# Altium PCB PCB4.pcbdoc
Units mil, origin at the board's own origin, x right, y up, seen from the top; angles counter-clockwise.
Board outline 2790 x 2690 mil, 2 copper layers (Top Layer, Bottom Layer); 2 components, 14 nets, 61 pads, 83 vias.
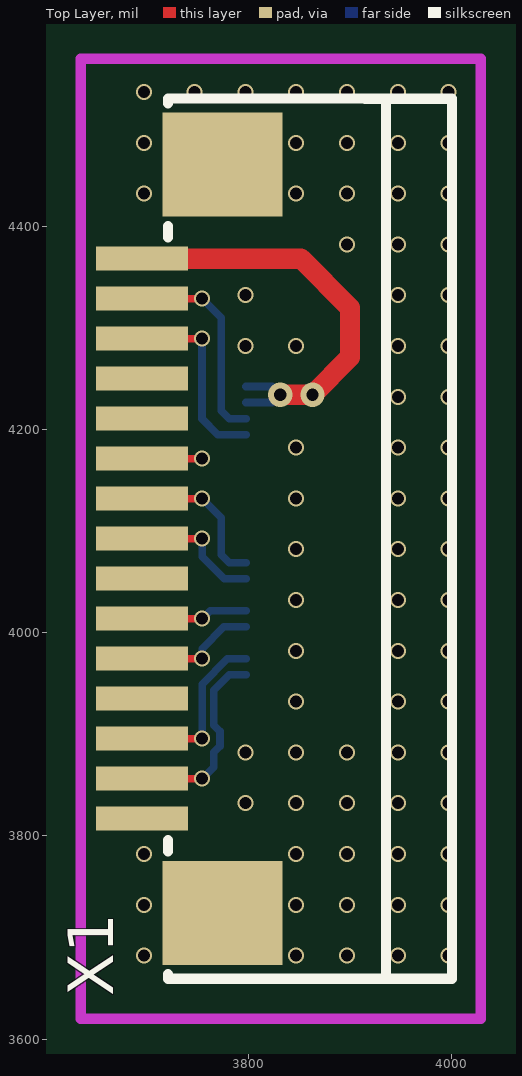
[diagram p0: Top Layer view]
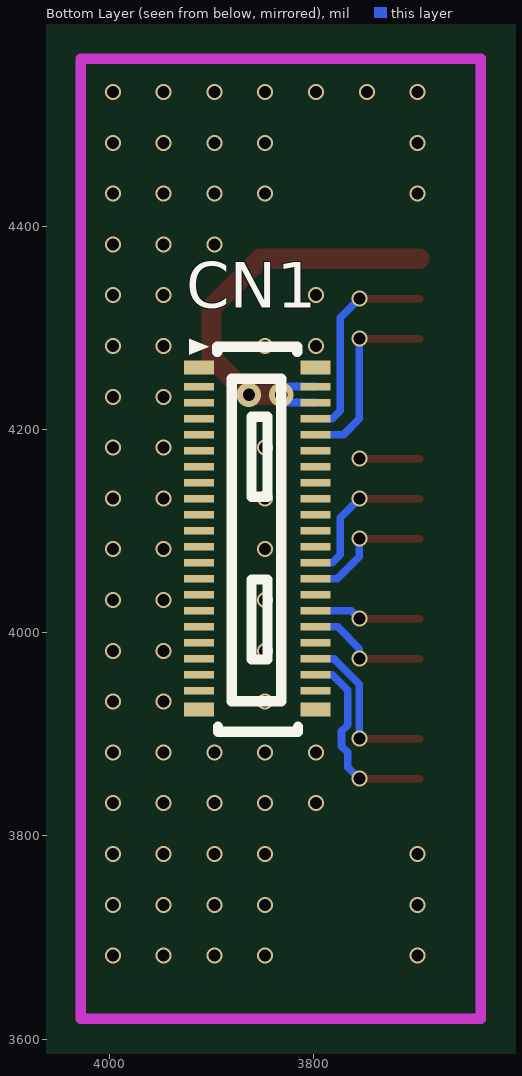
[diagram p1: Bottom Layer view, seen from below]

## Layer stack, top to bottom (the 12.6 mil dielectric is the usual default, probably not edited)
Top Layer: signal copper (thickness not stored)
Dielectric: dielectric 12.6, FR-4, Dk 4.8
Bottom Layer: signal copper (thickness not stored)

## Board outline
5540,2750 2750,2750 2750,5440 5540,5440

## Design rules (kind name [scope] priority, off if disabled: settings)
BoardOutlineClearance copperThickness1oz [All] p0: genericclearance=10 ignorepadtopadclearanceinfootprint=FALSE except(0: Arc-SplitContinuation Track-SplitContinuation SMDPad-SplitContinuation THPad-SplitContinuation Via-SplitContinuation Fill-SplitContinuation Poly-SplitContinuation Region-SplitContinuation Text-SplitContinuation; 6: Track-CutoutEdge SMDPad-CutoutEdge THPad-CutoutEdge Via-CutoutEdge Region-CutoutEdge; 11.8: Track-OutlineEdge SMDPad-OutlineEdge THPad-OutlineEdge Via-OutlineEdge Fill-OutlineEdge Region-OutlineEdge Poly-OutlineEdge Text-OutlineEdge Fill-CutoutEdge)
BoardOutlineClearance copperThickness2oz [All] p0: genericclearance=10 ignorepadtopadclearanceinfootprint=FALSE except(0: Arc-SplitContinuation Track-SplitContinuation SMDPad-SplitContinuation THPad-SplitContinuation Via-SplitContinuation Fill-SplitContinuation Poly-SplitContinuation Region-SplitContinuation Text-SplitContinuation; 6: Track-CutoutEdge SMDPad-CutoutEdge THPad-CutoutEdge Via-CutoutEdge Region-CutoutEdge; 11.8: Track-OutlineEdge SMDPad-OutlineEdge THPad-OutlineEdge Via-OutlineEdge Fill-OutlineEdge Region-OutlineEdge Poly-OutlineEdge Text-OutlineEdge Fill-CutoutEdge)
Clearance copperThickness1oz [(InNet('GND') OR InNet('CSID0N') OR InNet('CSID0P') OR InNet('CSID1N') OR InNet('CSID1P') OR InNet('CSICN') OR InNet('CSICP') OR InNet('CSID2N') OR InNet('CSID2P') OR InNet('CSID3N') OR InNet('CSID3P') OR InNet('HOST_SCL') OR InNet('HOST_SDA') OR InNet('3V3'))] p1: gap=7 ignorepadtopadclearanceinfootprint=FALSE except(4: Track-Track; 6: Track-SMDPad SMDPad-SMDPad Track-THPad SMDPad-THPad THPad-THPad Track-Via SMDPad-Via THPad-Via Via-Via SMDPad-Fill THPad-Fill Via-Fill Fill-Fill Track-Region SMDPad-Region THPad-Region Via-Region Region-Region Track-Poly SMDPad-Poly THPad-Poly Via-Poly Fill-Poly Region-Poly Poly-Poly Track-Text SMDPad-Text THPad-Text Via-Text Fill-Text Region-Text Poly-Text Text-Text; 6.9: Track-Hole SMDPad-Hole THPad-Hole Via-Hole Fill-Hole Region-Hole Poly-Hole Text-Hole Sheet-Hole; 11.8: Track-Fill Fill-Region Track-Sheet SMDPad-Sheet THPad-Sheet Via-Sheet Fill-Sheet Region-Sheet Poly-Sheet Text-Sheet)
Clearance copperThickness2oz [All] p1: gap=7 ignorepadtopadclearanceinfootprint=FALSE except(6: Track-SMDPad SMDPad-SMDPad Track-THPad SMDPad-THPad THPad-THPad Track-Via SMDPad-Via THPad-Via Via-Via SMDPad-Fill THPad-Fill Via-Fill Fill-Fill Track-Region SMDPad-Region THPad-Region Via-Region Region-Region Track-Poly SMDPad-Poly THPad-Poly Via-Poly Fill-Poly Region-Poly Poly-Poly Track-Text SMDPad-Text THPad-Text Via-Text Fill-Text Region-Text Poly-Text Text-Text; 6.9: Track-Hole SMDPad-Hole THPad-Hole Via-Hole Fill-Hole Region-Hole Poly-Hole Text-Hole Sheet-Hole; 8: Track-Track; 11.8: Track-Fill Fill-Region Track-Sheet SMDPad-Sheet THPad-Sheet Via-Sheet Fill-Sheet Region-Sheet Poly-Sheet Text-Sheet)
DiffPairsRouting differentialPair [All] p1: maxuncoupledlength=10 minlimit=6 maxlimit=6 mostfreqgap=6 toplayer_minwidth=5 toplayer_prefwidth=10 toplayer_maxwidth=100 bottomlayer_minwidth=5 bottomlayer_prefwidth=10 bottomlayer_maxwidth=100
PasteMaskExpansion pasteMaskExpansion [All] p1: expansion=0
PlaneConnect innerPlane [All] p1: planeconnectstyle=Relief reliefexpansion=20 reliefentries=4 reliefconductorwidth=10 reliefairgap=10
PolygonConnect copperRegion [All] p1: connectstyle=Direct reliefentries=4 reliefconductorwidth=10 polygonreliefangle="90 Angle" airgapwidth=10
RoutingVias viaSize [All] p1: viastyle="Through Hole" holewidth=11.811 minholewidth=11.8 maxholewidth=248 width=15.748 minwidth=15.748 maxwidth=393.7
SolderMaskExpansion solderMaskExpansion [All] p1: useseparateexpansions=TRUE expansion=2 expansionbottom=2
Width copperThickness1oz [All] p1: maxlimit=100 minlimit=5 preferedwidth=10
Width copperThickness2oz [All] p1: maxlimit=100 minlimit=8 preferedwidth=10

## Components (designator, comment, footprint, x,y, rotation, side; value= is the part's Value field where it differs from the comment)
CN1 "DF40C-40DP-0.4V(51)" CONN-SMD_DF40C-40DP-0.4V 3855,4092.56 r270 bottom
X1 "AFA07-S15ECA-00" FPC-SMD_15P-P1.00_JS_AFA07-S15XXX 3735,4092.56 r90 top

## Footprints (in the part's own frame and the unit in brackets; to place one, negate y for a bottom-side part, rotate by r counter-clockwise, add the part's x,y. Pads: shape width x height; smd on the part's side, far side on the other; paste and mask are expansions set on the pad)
CONN-SMD_DF40C-40DP-0.4V [mm]
  rect 0.19x0.75 smd: 1(-3.8,-1.455) 2(-3.8,1.455) 3(-3.4,-1.455) 4(-3.4,1.455) 5(-3,-1.455) 6(-3,1.455) 7(-2.6,-1.455) 8(-2.6,1.455) 9(-2.2,-1.455) 10(-2.2,1.455) 11(-1.8,-1.455) 12(-1.8,1.455) 13(-1.4,-1.455) 14(-1.4,1.455) 15(-1,-1.455) 16(-1,1.455) 17(-0.6,-1.455) 18(-0.6,1.455) 19(-0.2,-1.455) 20(-0.2,1.455) 21(0.2,-1.455) 22(0.2,1.455) 23(0.6,-1.455) 24(0.6,1.455) 25(1,-1.455) 26(1,1.455) 27(1.4,-1.455) 28(1.4,1.455) 29(1.8,-1.455) 30(1.8,1.455) 31(2.2,-1.455) 32(2.2,1.455) 33(2.6,-1.455) 34(2.6,1.455) 35(3,-1.455) 36(3,1.455) 37(3.4,-1.455) 38(3.4,1.455) 39(3.8,-1.455) 40(3.8,1.455)
  rect 0.35x0.75 smd: 41(4.275,-1.455) 42(4.275,1.455) 43(-4.275,1.455) 44(-4.275,-1.455)
  silkscreen extent -5,-1.7 4.83,1.02
FPC-SMD_15P-P1.00_JS_AFA07-S15XXX [mm]
  rect 0.6x2.3 smd: 1(-7,1.009) 2(-6,1.009) 3(-5,1.009) 4(-4,1.009) 5(-3,1.009) 6(-2,1.009) 7(-1,1.009) 8(0,1.009) 9(1,1.009) 10(2,1.01) 11(3,1.01) 12(4,1.01) 13(5,1.01) 14(6,1.009) 15(7,1.01)
  rect 2.6x3 smd: 16(9.352,-1.01) 17(-9.352,-1.01)
  silkscreen extent -11,-6.74 11,0.36

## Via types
v1: diameter 15.75, hole 11.81, Top Layer to Bottom Layer, 81 vias
v2: diameter 24.02, hole 12.01, Top Layer to Bottom Layer, 2 vias

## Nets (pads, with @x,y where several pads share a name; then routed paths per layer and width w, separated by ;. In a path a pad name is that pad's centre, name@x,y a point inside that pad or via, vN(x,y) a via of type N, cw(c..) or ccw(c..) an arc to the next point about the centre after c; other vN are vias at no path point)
3V3: CN1.2 CN1.4 X1.15 | length 431.2
  Top Layer w20: X1.15 3851.85,4368.15 3900,4320 3900,4271.2 v2(3863.16,4234.36) v2@3831.43,4234.36
  Bottom Layer w7.9: CN1.4 3823.48,4226.42 v2(3831.38,4234.31) 3823.52,4242.17 CN1.2
CSICN: CN1.26 X1.8 | length 129
  Top Layer w7.5: X1.8 v1(3754.44,4092.56)
  Bottom Layer w7.5: v1(3754.44,4092.56) 3754.44,4075 3776.26,4053.19 CN1.26
CSICP: CN1.24 X1.9 | length 149.8
  Top Layer w7.5: X1.9 v1(3754.44,4131.93)
  Bottom Layer w7.5: v1(3754.44,4131.93) 3773.2,4113.18 3773.2,4076.91 3781.17,4068.94 CN1.24
CSID0N: CN1.38 X1.2 | length 194.2
  Top Layer w7.5: X1.2 v1(3754.44,3856.34)
  Bottom Layer w7.5: v1(3754.44,3856.34) 3765.94,3867.84 3765.94,3882.29 3772.07,3888.41 3772.07,3903.01 3765.94,3909.14 3765.94,3943.48 3781.17,3958.71 CN1.38
CSID0P: CN1.36 X1.3 | length 166.5
  Top Layer w7.5: X1.3 v1(3754.44,3895.71)
  Bottom Layer w7.5: v1(3754.44,3895.71) 3754.44,3949.44 3779.45,3974.45 CN1.36
CSID1N: CN1.32 X1.5 | length 121.3
  Top Layer w7.5: X1.5 v1(3754.44,3974.45)
  Bottom Layer w7.5: v1(3754.44,3974.45) 3754.44,3984.44 3775.95,4005.95 CN1.32
CSID1P: CN1.30 X1.6 | length 105.7
  Top Layer w7.5: X1.6 v1(3754.44,4013.81)
  Bottom Layer w7.5: v1(3754.44,4013.81) 3762.32,4021.7 CN1.30
CSID2N: CN1.20
CSID2P: CN1.18
CSID3N: CN1.14
CSID3P: CN1.12
GND: CN1.10 CN1.16 CN1.22 CN1.28 CN1.34 CN1.40 CN1.41 CN1.42 CN1.43 CN1.44 X1.1 X1.4 X1.7 X1.10 X1.16 X1.17 | length 59.1
  Top Layer w7.5: X1.10 v1(3754.38,4171.3)
  other v1: 3697.1,3682.22 3847.1,3682.22 3897.1,3682.22 3947.1,3682.22 3997.1,3682.22 3697.1,3732.22 3847.1,3732.22 3897.1,3732.22 3947.1,3732.22 3997.1,3732.22 3697.1,3782.22 3847.1,3782.22 3897.1,3782.22 3947.1,3782.22 3997.1,3782.22 3797.1,3832.22 3847.1,3832.22 3897.1,3832.22 3947.1,3832.22 3997.1,3832.22 3797.1,3882.22 3847.1,3882.22 3897.1,3882.22 3947.1,3882.22 3997.1,3882.22 3847.1,3932.22 3947.1,3932.22 3997.1,3932.22 3847.1,3982.22 3947.1,3982.22 3997.1,3982.22 3847.1,4032.22 3947.1,4032.22 3997.1,4032.22 3847.1,4082.22 3947.1,4082.22 3997.1,4082.22 3847.1,4132.22 3947.1,4132.22 3997.1,4132.22 3847.1,4182.22 3947.1,4182.22 3997.1,4182.22 3947.1,4232.22 3997.1,4232.22 3797.1,4282.22 3847.1,4282.22 3947.1,4282.22 3997.1,4282.22 3797.1,4332.22 3947.1,4332.22 3997.1,4332.22 3897.1,4382.22 3947.1,4382.22 3997.1,4382.22 3697.1,4432.22 3847.1,4432.22 3897.1,4432.22 3947.1,4432.22 3997.1,4432.22 3697.1,4482.22 3847.1,4482.22 3897.1,4482.22 3947.1,4482.22 3997.1,4482.22 3697.1,4532.22 3747.1,4532.22 3797.1,4532.22 3847.1,4532.22 3897.1,4532.22 3947.1,4532.22 3997.1,4532.22
HOST_SCL: CN1.8 X1.13 | length 187.8
  Top Layer w7.5: X1.13 v1(3754.38,4289.41)
  Bottom Layer w7.5: v1(3754.38,4289.41) 3754.38,4210.62 3770.07,4194.93 CN1.8
HOST_SDA: CN1.6 X1.14 | length 204.9
  Top Layer w7.5: X1.14 v1(3754.44,4328.78)
  Bottom Layer w7.5: v1(3754.44,4328.78) 3773.2,4310.03 3773.2,4218.64 3781.17,4210.67 CN1.6
pads on no net: CN1.1 CN1.3 CN1.5 CN1.7 CN1.9 CN1.11 CN1.13 CN1.15 CN1.17 CN1.19 CN1.21 CN1.23 CN1.25 CN1.27 CN1.29 CN1.31 CN1.33 CN1.35 CN1.37 CN1.39 X1.11 X1.12

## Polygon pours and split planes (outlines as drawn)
GND on Top Layer (solid, remove dead copper, pour order 0): 3170,4665 4890,4665 4890,3325 3170,3325
GND on Bottom Layer (solid, remove dead copper, pour order 4): 3000,5190 5290,5190 5290,3000 3000,3000
3V3 on Bottom Layer (solid, remove dead copper, pour order 2): 3782,4246.56 3878,4246.56 3878,4221.56 3782,4221.56

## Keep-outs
Board Outline Layer:
  lines w10: 3635,3620.12 4028.7,3620.12 4028.7,4565 3635,4565 3635,3620.12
